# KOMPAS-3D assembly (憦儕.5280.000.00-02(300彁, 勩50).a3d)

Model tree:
1. Плоскость XY
2. Плоскость ZX
3. Плоскость ZY
4. Ось X
5. Ось Y
6. Ось Z
7. Начало координат  (labels: Операция без истории:1; ␣3␣3; ␣5␣ĵ; ␣6)

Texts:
  Линия-выноска #1
  Линия-выноска #2
  Линия-выноска #3
  Отклонения формы и база
  Марка координационной оси
  Марка/позиционное обозначение с линией-выноской
  Марка/позиционное обозначение на линии
  Марка/позиционное обозначение без линии-выноски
